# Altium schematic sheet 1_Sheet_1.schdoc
size 464 x 312 mm; Name: A_Customize; Symbol: A_Customize; Device: A_Customize; @Project Name: AGNI v3 latest; REV: 1.0; Date: 2025-07-25; Sheet: 1/1; Draw By: kavishraval8; Company: Your Company; Convert to PCB: yes; Add into BOM: yes; spicePre: .; @Page No: 1; @Page Count: 1; @Schematic Name: AGNI v3; @Board Name: AGNI v3; @Update Date: 2025-08-08; @Create Time: 12:50:48; @Update Time: 16:18:51; @Page Name: Sheet_1; @Create Date: 2025-08-08
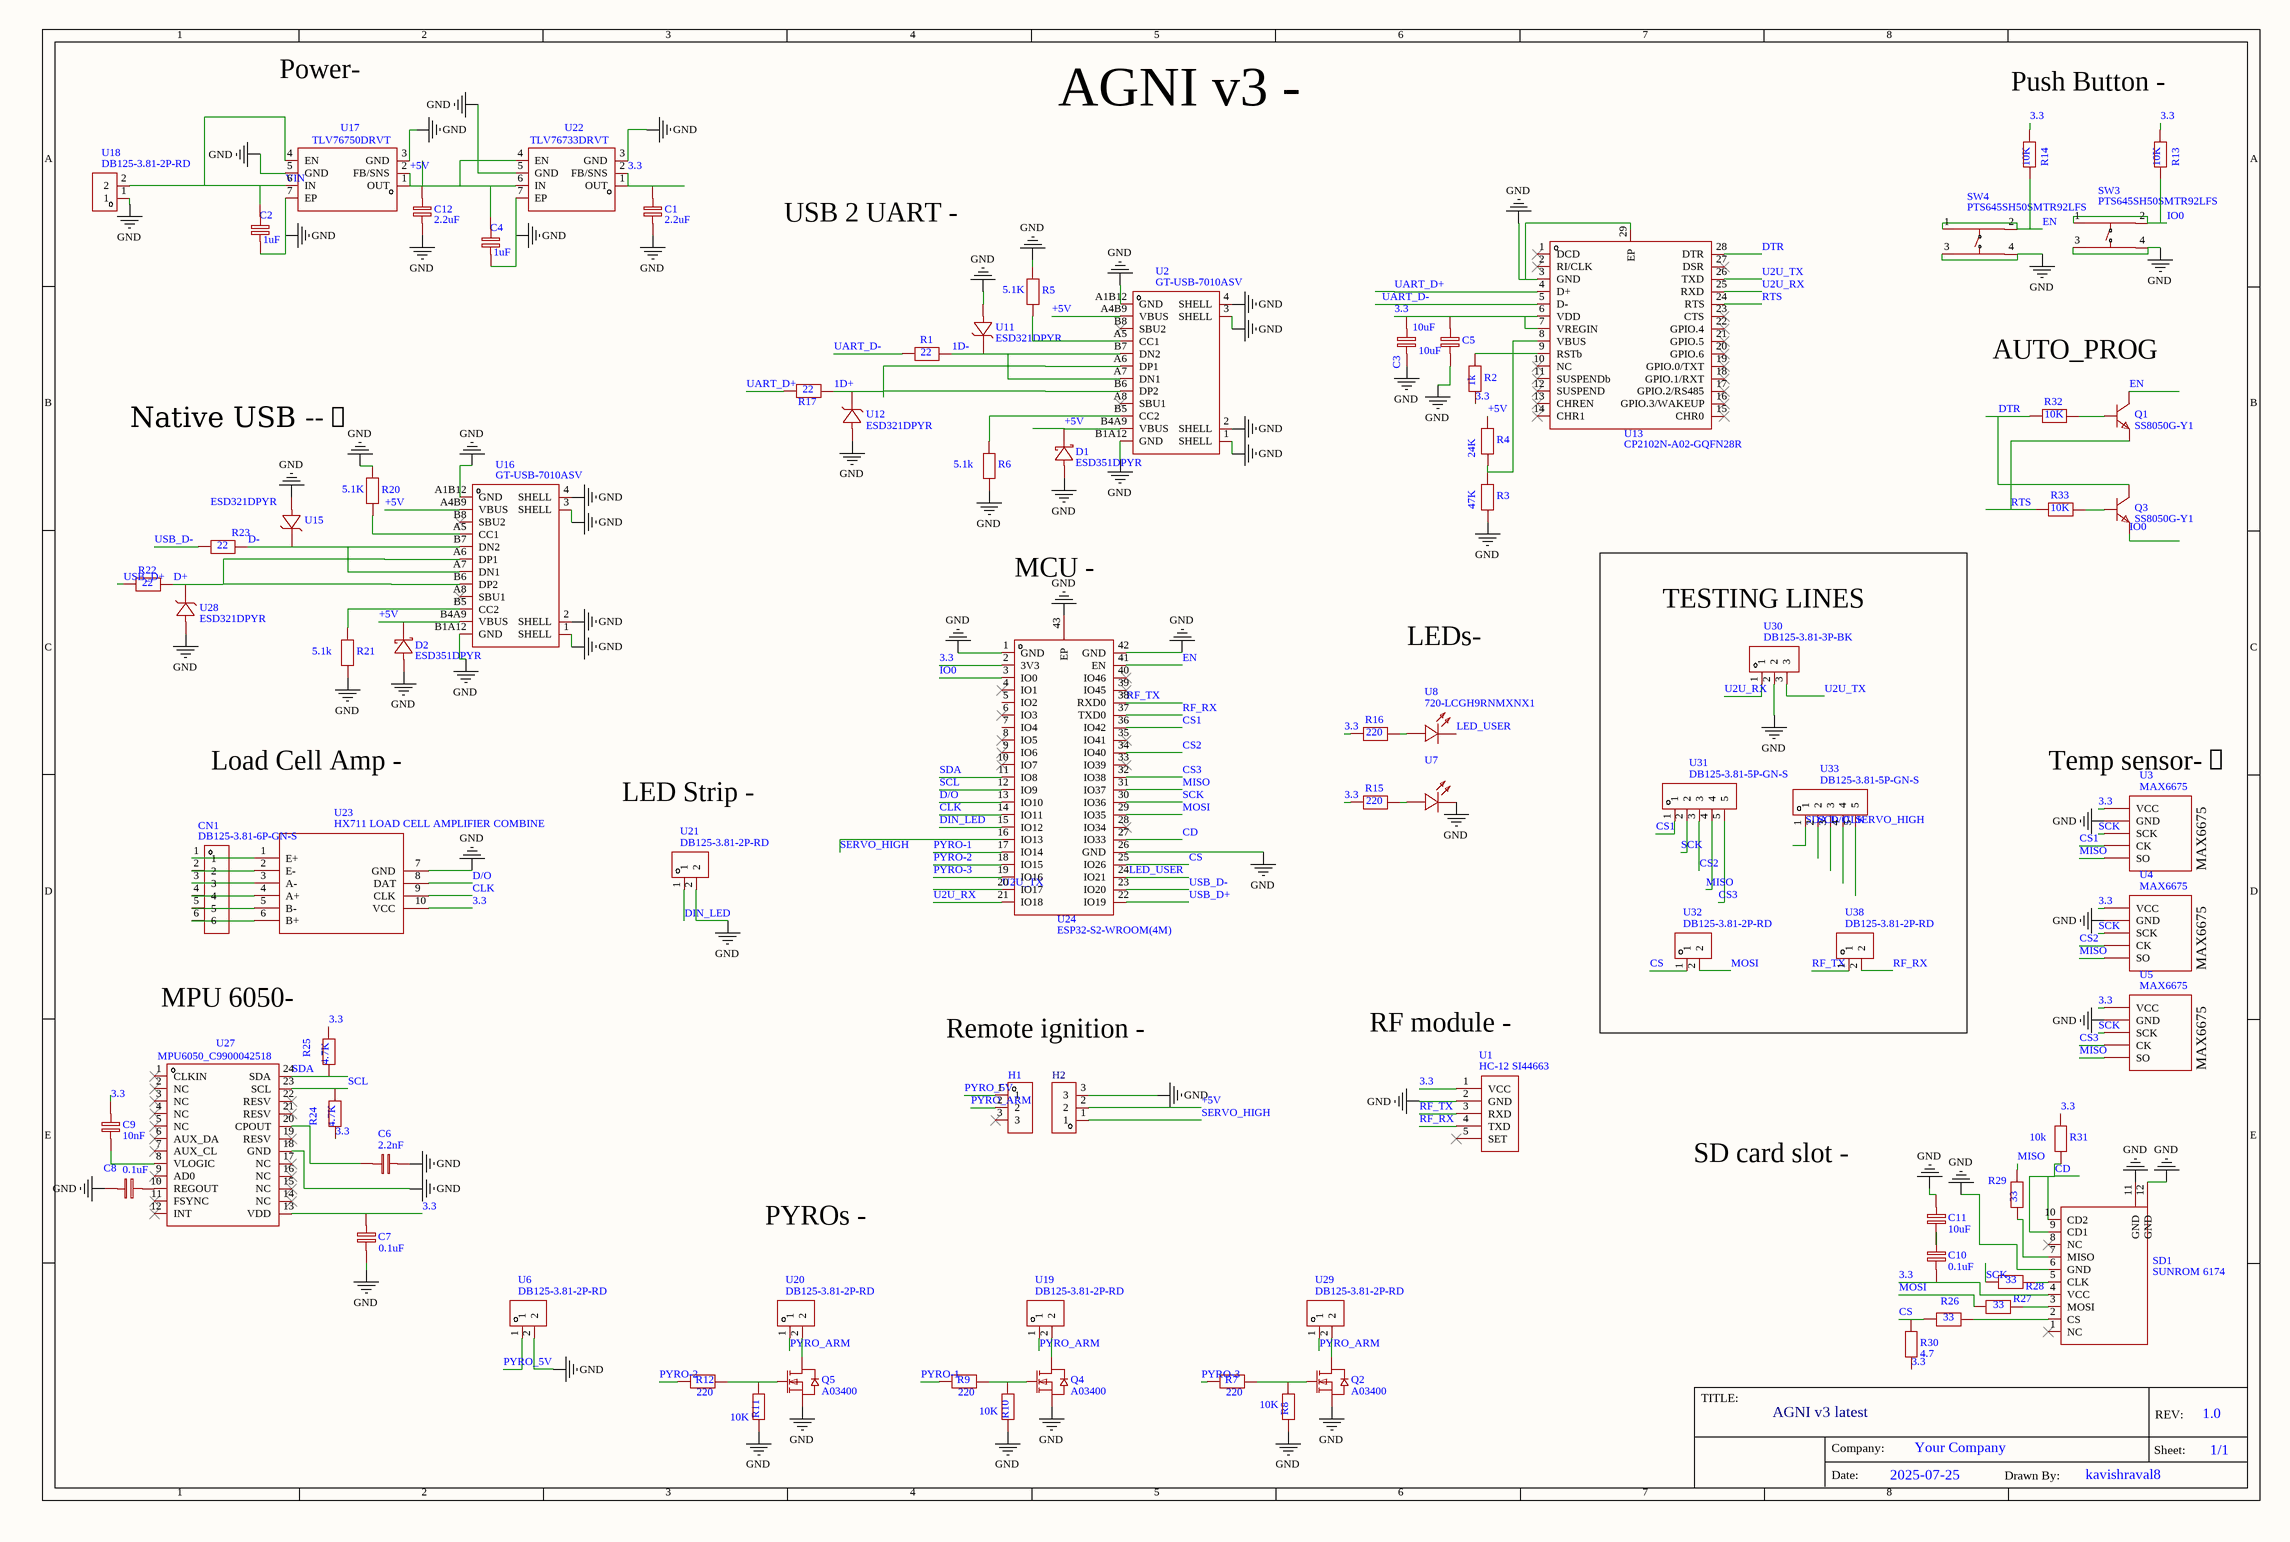
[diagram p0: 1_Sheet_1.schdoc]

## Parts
C1  2.2uF  [C0603]
C2  1uF  [C0603]
C3  10uF  [C0603]
C4  1uF  [C0603]
C5  10uF  [C0603]
C6  2.2nF  [C0603]
C7  0.1uF  [C0603]
C8  0.1uF  [C0603]
C9  10nF  [C0603]
C10  0.1uF  [C0603]
C11  10uF  [C0603]
C12  2.2uF  [C0603]
CN1  DB125-3.81-6P-GN-S  [CONN-TH_DB125-3.81-6P-GN-S]
D1  ESD351DPYR  [X1SON-2_L1.0-W0.6-P0.65-RD-1]
D2  ESD351DPYR  [X1SON-2_L1.0-W0.6-P0.65-RD-1]
H1  (no value)  [HDR-TH_3P-P2.54-V-M]
H2  (no value)  [HDR-TH_3P-P2.54-V-M]
Q1  SS8050G-Y1  [SOT-23-3_L2.9-W1.3-P1.90-LS2.4-BR]
Q2  A03400  [SOT-23-3_L2.9-W1.3-P1.90-LS2.6-BR]
Q3  SS8050G-Y1  [SOT-23-3_L2.9-W1.3-P1.90-LS2.4-BR]
Q4  A03400  [SOT-23-3_L2.9-W1.3-P1.90-LS2.6-BR]
Q5  A03400  [SOT-23-3_L2.9-W1.3-P1.90-LS2.6-BR]
R1  22  [R0603]
R2  1k  [R0603]
R3  47K  [R0603]
R4  24K  [R0603]
R5  5.1K  [R0603]
R6  5.1k  [R0603]
R7  220  [R0603]
R8  10K  [R0603]
R9  220  [R0603]
R10  10K  [R0603]
R11  10K  [R0603]
R12  220  [R0603]
R13  10K  [R0603]
R14  10K  [R0603]
R15  220  [R0603]
R16  220  [R0603]
R17  22  [R0603]
R20  5.1K  [R0603]
R21  5.1k  [R0603]
R22  22  [R0603]
R23  22  [R0603]
R24  4.7K  [R0603]
R25  4.7K  [R0603]
R26  33  [R0603]
R27  33  [R0603]
R28  33  [R0603]
R29  33  [R0603]
R30  4.7  [R0603]
R31  10k  [R0603]
R32  10K  [R0603]
R33  10K  [R0603]
SD1  SUNROM 6174  [SUNROM 6174]
SW3  PTS645SH50SMTR92LFS  [KEY-SMD_4P-L6.0-W6.0-P4.50-LS9.0]
SW4  PTS645SH50SMTR92LFS  [KEY-SMD_4P-L6.0-W6.0-P4.50-LS9.0]
U1  HC-12 SI44663  [HC-12 SI4463 WIRELESS MODULE]
U2  GT-USB-7010ASV  [USB-C-SMD_G-SWITCH_GT-USB-7010ASV]
U3  MAX6675  [MAX6675]
U4  MAX6675  [MAX6675]
U5  MAX6675  [MAX6675]
U6  DB125-3.81-2P-RD  [CONN-TH_DB125-3.81-2P-RD]
U7  720-LCGH9RNMXNX1  [LED-SMD_SD65-120-LED]  (value not drawn)
U8  720-LCGH9RNMXNX1  [LED-SMD_SD65-120-LED]
U11  ESD321DPYR  [X1SON-2_L1.0-W0.6-P0.65-RD]
U12  ESD321DPYR  [X1SON-2_L1.0-W0.6-P0.65-RD]
U13  CP2102N-A02-GQFN28R  [QFN-28_L5.0-W5.0-P0.50-TL-EP3.3]
U15  ESD321DPYR  [X1SON-2_L1.0-W0.6-P0.65-RD]
U16  GT-USB-7010ASV  [USB-C-SMD_G-SWITCH_GT-USB-7010ASV]
U17  TLV76750DRVT  [WSON-6_L2.0-W2.0-P0.65-TL-EP]
U18  DB125-3.81-2P-RD  [CONN-TH_DB125-3.81-2P-RD]
U19  DB125-3.81-2P-RD  [CONN-TH_DB125-3.81-2P-RD]
U20  DB125-3.81-2P-RD  [CONN-TH_DB125-3.81-2P-RD]
U21  DB125-3.81-2P-RD  [CONN-TH_DB125-3.81-2P-RD]
U22  TLV76733DRVT  [WSON-6_L2.0-W2.0-P0.65-TL-EP]
U23  HX711 LOAD CELL AMPLIFIER COMBINE  [HX711 LOAD CELL AMPLIFIER HX711 BREAKOUT]
U24  ESP32-S2-WROOM(4M)  [WIFI-SMD_ESP32-S2-WROVER-I]
U27  MPU6050_C9900042518  [QFN-24_L4.0-W4.0-P0.50-BL]
U28  ESD321DPYR  [X1SON-2_L1.0-W0.6-P0.65-RD]
U29  DB125-3.81-2P-RD  [CONN-TH_DB125-3.81-2P-RD]
U30  DB125-3.81-3P-BK  [CONN-TH_DB125-3.81-3P-BK]
U31  DB125-3.81-5P-GN-S  [CONN-TH_DB125-3.81-5P-GN-S]
U32  DB125-3.81-2P-RD  [CONN-TH_DB125-3.81-2P-RD]
U33  DB125-3.81-5P-GN-S  [CONN-TH_DB125-3.81-5P-GN-S]
U38  DB125-3.81-2P-RD  [CONN-TH_DB125-3.81-2P-RD]

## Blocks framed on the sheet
TESTING LINES: U30-U33 U38

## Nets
GND: C1.1 C2.1 C3.1 C4.1 C5.1 C6.1 C7.2 C8.1 C11.1 C12.1 D1.2(A) D2.2(A) H2.3 Q2.2(S) Q4.2(S) Q5.2(S) R3.2 R5.1 R6.1 R8.1 R10.1 R11.1 R20.1 R21.1 SD1.6(GND) SD1.11(GND) SD1.12(GND) SW3.3 SW3.4 SW4.3 SW4.4 U1.2(GND) U2.1(SHELL) U2.2(SHELL) U2.3(SHELL) U2.4(SHELL) U2.A1B12(GND) U2.B1A12(GND) U3.4(GND) U4.4(GND) U5.4(GND) U6.2 U7.1(K) U11.2(A) U12.2(A) U13.3(GND) U13.29(EP) U15.2(A) U16.1(SHELL) U16.2(SHELL) U16.3(SHELL) U16.4(SHELL) U16.A1B12(GND) U16.B1A12(GND) U17.3(GND) U17.5(GND) U17.7(EP) U18.1 U21.2 U22.3(GND) U22.5(GND) U22.7(EP) U23.7(GND) U24.1(GND) U24.26(GND) U24.42(GND) U24.43(EP) U27.18(GND) U28.2(A) U30.2
1D+: R17.2 U2.A6(DP1) U2.B6(DP2) U12.1(K)
1D-: R1.2 U2.A7(DN1) U2.B7(DN2) U11.1(K)
3.3: C1.2 C3.2 C5.2 C7.1 C9.2 C10.2 R2.2 R13.2 R14.2 R15.2 R16.2 R24.1 R25.2 R30.1 R31.1 SD1.4(VCC) U1.1(VCC) U3.5(VCC) U4.5(VCC) U5.5(VCC) U13.6(VDD) U13.7(VREGIN) U22.1(OUT) U22.2(FB/SNS) U23.10(VCC) U24.2(3V3) U27.13(VDD)
+5V: C4.2 C12.2 D1.1(K) D2.1(K) H2.2 R4.1 U2.A4B9(VBUS) U2.B4A9(VBUS) U16.A4B9(VBUS) U16.B4A9(VBUS) U17.1(OUT) U17.2(FB/SNS) U22.4(EN) U22.6(IN)
CD: R31.2 SD1.9(CD1) SD1.10(CD2) U24.27(IO33)
CLK: U23.9(CLK) U24.14(IO11) U33.4
CS: R26.2 R30.2 U24.25(IO26) U32.1
CS1: U3.2(CK) U24.36(IO42) U31.1
CS2: U4.2(CK) U24.34(IO40) U31.3
CS3: U5.2(CK) U24.32(IO38) U31.5
D+: R22.2 U16.A6(DP1) U16.B6(DP2) U28.1(K)
D-: R23.2 U15.1(K) U16.A7(DN1) U16.B7(DN2)
D/O: U23.8(DAT) U24.13(IO10) U33.3
DIN_LED: U21.1 U24.15(IO12)
DTR: Q3.3(C) R32.2 U13.28(DTR)
EN: Q1.3(C) R14.1 SW4.1 SW4.2 U24.41(EN)
IO0: Q3.2(E) R13.1 SW3.1 SW3.2 U24.3(IO0)
LED_USER: U8.1(K) U24.24(IO21)
MISO: R29.2 U3.1(SO) U4.1(SO) U5.1(SO) U24.31(IO37) U31.4
MOSI: R27.2 U24.29(IO35) U32.2
PYRO-1: R9.1 U24.17(IO14)
PYRO-2: R12.1 U24.18(IO15)
PYRO-3: R7.1 U24.19(IO16)
PYRO_5V: H1.1 U6.1
PYRO_ARM: H1.2 U19.1 U20.1 U29.1
RF_RX: U1.4(TXD) U24.37(TXD0) U38.2
RF_TX: U1.3(RXD) U24.38(RXD0) U38.1
RTS: Q1.2(E) R33.2 U13.24(RTS)
SCK: R28.2 U3.3(SCK) U4.3(SCK) U5.3(SCK) U24.30(IO36) U31.2
SCL: R24.2 U24.12(IO9) U27.23(SCL) U33.2
SDA: R25.1 U24.11(IO8) U27.24(SDA) U33.1
SERVO_HIGH: H2.1 U24.16(IO13) U33.5
U2U_RX: U13.25(RXD) U24.21(IO18) U30.1
U2U_TX: U13.26(TXD) U24.20(IO17) U30.3
UART_D+: R17.1 U13.4(D+)
UART_D-: R1.1 U13.5(D-)
USB_D+: R22.1 U24.22(IO19)
USB_D-: R23.1 U24.23(IO20)
VIN: C2.2 U17.4(EN) U17.6(IN) U18.2
NetC6_2: C6.2 U27.20(CPOUT)
NetC8_2: C8.2 U27.10(REGOUT)
NetC9_1: C9.1 U27.8(VLOGIC)
NetC10_1: C10.1 C11.2
NetCN1_1: CN1.1 U23.1(E+)
NetCN1_2: CN1.2 U23.2(E-)
NetCN1_3: CN1.3 U23.3(A-)
NetCN1_4: CN1.4 U23.4(A+)
NetCN1_5: CN1.5 U23.5(B-)
NetCN1_6: CN1.6 U23.6(B+)
NetQ1_1: Q1.1(B) R32.1
NetQ2_1: Q2.1(G) R7.2 R8.2
NetQ2_3: Q2.3(D) U29.2
NetQ3_1: Q3.1(B) R33.1
NetQ4_1: Q4.1(G) R9.2 R10.2
NetQ4_3: Q4.3(D) U19.2
NetQ5_1: Q5.1(G) R11.2 R12.2
NetQ5_3: Q5.3(D) U20.2
NetR2_1: R2.1 U13.9(RSTb)
NetR3_1: R3.1 R4.2 U13.8(VBUS)
NetR5_2: R5.2 U2.A5(CC1)
NetR6_2: R6.2 U2.B5(CC2)
NetR15_1: R15.1 U7.2(A)
NetR16_1: R16.1 U8.2(A)
NetR20_2: R20.2 U16.A5(CC1)
NetR21_2: R21.2 U16.B5(CC2)
NetR26_1: R26.1 SD1.2(CS)
NetR27_1: R27.1 SD1.3(MOSI)
NetR28_1: R28.1 SD1.5(CLK)
NetR29_1: R29.1 SD1.7(MISO)

Not connected (* = marked no-connect by the designer): H1 3*; SD1 1(NC)* 8(NC)*; U1 5(SET)*; U2 A8(SBU1)* B8(SBU2)*; U13 1(DCD)* 2(RI/CLK)* 10(NC)* 11(SUSPENDb)* 12(SUSPEND)* 13(CHREN)* 14(CHR1)* 15(CHR0)* 16(GPIO.3/WAKEUP)* 17(GPIO.2/RS485)* 18(GPIO.1/RXT)* 19(GPIO.0/TXT)* 20(GPIO.6)* 21(GPIO.5)* 22(GPIO.4)* 23(CTS)* 27(DSR)*; U16 A8(SBU1)* B8(SBU2)*; U24 4(IO1)* 5(IO2) 6(IO3)* 7(IO4) 8(IO5)* 9(IO6)* 10(IO7)* 28(IO34)* 33(IO39)* 35(IO41)* 39(IO45)* 40(IO46)*; U27 1(CLKIN)* 2(NC)* 3(NC)* 4(NC)* 5(NC)* 6(AUX_DA)* 7(AUX_CL)* 9(AD0)* 11(FSYNC)* 12(INT)* 14(NC)* 15(NC)* 16(NC)* 17(NC)* 19(RESV)* 21(RESV)* 22(RESV)*

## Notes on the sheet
- Power-
- AGNI v3 -
- Push Button -
- USB 2 UART -
- AUTO_PROG
- Native USB -‍-️
- MCU -
- LEDs-
- Load Cell Amp -
- LED Strip -
- (near U3) Temp sensor-️
- MPU 6050-
- Remote ignition -
- RF module -
- SD card slot -
- PYROs -

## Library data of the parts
C1 C12 = 2.2uF: Convert to PCB: yes; nameAlias: Value(F); Contributor: LCEDA_Lib
C2 C4 = 1uF: Convert to PCB: yes; nameAlias: Value(F); Contributor: LCEDA_Lib
C3 C5 C11 = 10uF: Convert to PCB: yes; nameAlias: Value(F); Contributor: LCEDA_Lib
C6 = 2.2nF: Convert to PCB: yes; nameAlias: Value(F); Contributor: LCEDA_Lib
C7 C8 C10 = 0.1uF: Convert to PCB: yes; nameAlias: Value(F); Contributor: LCEDA_Lib
C9 = 10nF: Convert to PCB: yes; nameAlias: Value(F); Contributor: LCEDA_Lib
CN1 = DB125-3.81-6P-GN-S: Manufacturer: DORABO(地博电气); Convert to PCB: yes; Contributor: va2thc
D1 D2 = ESD351DPYR: Manufacturer: TI(德州仪器); Convert to PCB: yes; Contributor: LCSC
H1 H2 = HDR-M_2.54_1x3P: Symbol: PZ254V-11-03P_C2937625; Convert to PCB: yes
Q1 Q3 = SS8050G-Y1: Manufacturer: GME(银河微电); Convert to PCB: yes; Contributor: LCSC
Q2 Q4 Q5 = A03400: Manufacturer: TRR(明德微); Manufacturer Part: AO3400; Convert to PCB: yes; Contributor: lcsc
R1 R17 R22 R23 = 22: Convert to PCB: yes; nameAlias: Value(Ω); Contributor: LCEDA_Lib
R2 = 1k: Convert to PCB: yes; nameAlias: Value(Ω); Contributor: LCEDA_Lib
R3 = 47K: Convert to PCB: yes; nameAlias: Value(Ω); Contributor: LCEDA_Lib
R4 = 24K: Convert to PCB: yes; nameAlias: Value(Ω); Contributor: LCEDA_Lib
R5 R20 = 5.1K: Convert to PCB: yes; nameAlias: Value(Ω); Contributor: LCEDA_Lib
R6 R21 = 5.1k: Convert to PCB: yes; nameAlias: Value(Ω); Contributor: LCEDA_Lib
R7 R9 R12 R15 R16 = 220: Convert to PCB: yes; nameAlias: Value(Ω); Contributor: LCEDA_Lib
R8 R10 R11 R13 R14 R32 R33 = 10K: Convert to PCB: yes; nameAlias: Value(Ω); Contributor: LCEDA_Lib
R24 R25 = 4.7K: Convert to PCB: yes; nameAlias: Value(Ω); Contributor: LCEDA_Lib
R26-R29 = 33: Convert to PCB: yes; nameAlias: Value(Ω); Contributor: LCEDA_Lib
R30 = 4.7: Convert to PCB: yes; nameAlias: Value(Ω); Contributor: LCEDA_Lib
R31 = 10k: Convert to PCB: yes; nameAlias: Value(Ω); Contributor: LCEDA_Lib
SD1 = SUNROM 6174: Convert to PCB: yes; Contributor: Vanya12345
SW3 SW4 = PTS645SH50SMTR92LFS: Manufacturer: C&K; Convert to PCB: yes; Contributor: LCSC
U1 = HC-12 SI44663: Convert to PCB: yes; Contributor: v_zhukov1985
U2 U16 = GT-USB-7010ASV: Manufacturer: G-Switch(品赞); Convert to PCB: yes; Contributor: lcsc
U3-U5 = MAX6675: Convert to PCB: yes; Contributor: umar1farooqui
U6 U18-U21 U29 U32 U38 = DB125-3.81-2P-RD: Manufacturer: DORABO(地博电气); Manufacturer Part: DB125-3.81-2P-RD-S; Convert to PCB: yes; Contributor: LCSC
U7 U8 = 720-LCGH9RNMXNX1: Manufacturer: null; Convert to PCB: yes; Contributor: lcsc
U11 U12 U15 U28 = ESD321DPYR: Manufacturer: null; Convert to PCB: yes; Contributor: LCSC
U13 = CP2102N-A02-GQFN28R: Manufacturer: SKYWORKS/SILICON LABS(芯科); Convert to PCB: yes; Contributor: LCSC
U17 = TLV76750DRVT: Manufacturer: TI(德州仪器); Convert to PCB: yes; Contributor: lcsc
U22 = TLV76733DRVT: Manufacturer: TI(德州仪器); Convert to PCB: yes; Contributor: LCSC
U23 = HX711 LOAD CELL AMPLIFIER COMBINE: Convert to PCB: yes; Contributor: Oh Qingxiang
U24 = ESP32-S2-WROOM(4M): Manufacturer: ESPRESSIF(乐鑫); Manufacturer Part: ESP32-S2-WROOM-N4; Convert to PCB: yes; Contributor: LCSC
U27 = MPU6050_C9900042518: Manufacturer: null; Convert to PCB: yes; Contributor: lcsc
U30 = DB125-3.81-3P-BK: Manufacturer: DORABO(地博电气); Manufacturer Part: DB125-3.81-3P-BK-S; Convert to PCB: yes; Contributor: LCSC
U31 U33 = DB125-3.81-5P-GN-S: Manufacturer: DORABO(地博电气); Convert to PCB: yes; Contributor: lcsc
